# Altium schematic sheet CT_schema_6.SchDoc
size 257 x 245 mm
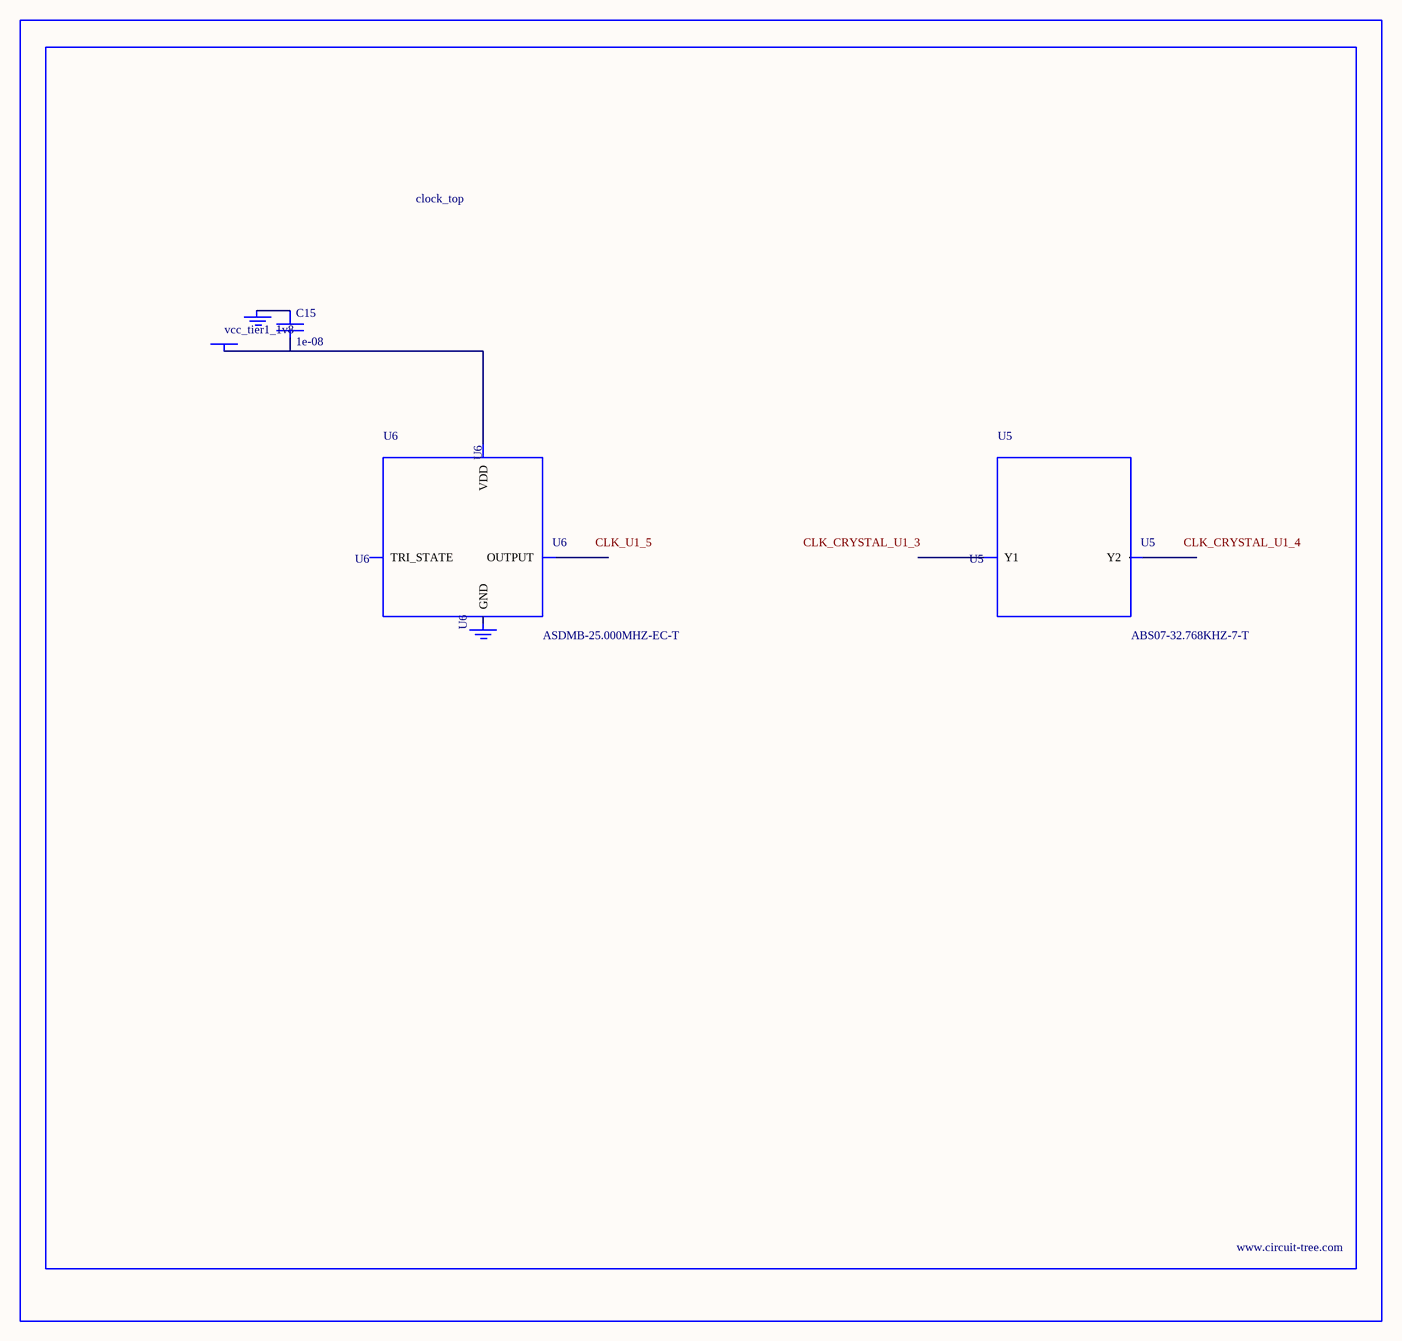
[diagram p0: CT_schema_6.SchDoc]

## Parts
BORDER5  (no value)
C15  1e-08  [C0402]
GND_INSTANCE_5_0  (no value)
GND_INSTANCE_5_1  (no value)
POWER_INSTANCE_5_0  vcc_tier1_1v8
U5  ABS07-32.768KHZ-7-T  [ABS07-32.768KHZ-7-T]
U6  ASDMB-25.000MHZ-EC-T  [ASDMB-XX.XXXXMHZ-XX-XX-XXX]

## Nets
NetC15_1: C15.1 GND_INSTANCE_5_0.0(GND)
NetC15_2: C15.2 POWER_INSTANCE_5_0.0(PWR) U6.4(VDD)

Not connected (* = marked no-connect by the designer): GND_INSTANCE_5_1 0(GND); U5 1(Y1) 2(Y2); U6 1(TRI_STATE) 2(GND) 3(OUTPUT)

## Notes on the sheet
- Labels drawn without touching a wire or pin: CLK_CRYSTAL_U1_3, CLK_CRYSTAL_U1_4, CLK_U1_5

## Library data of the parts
BORDER5 = BORDER_PAGE5
C15 = C0402C103K3RAC
GND_INSTANCE_5_0 GND_INSTANCE_5_1 = GND
POWER_INSTANCE_5_0 = PWR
